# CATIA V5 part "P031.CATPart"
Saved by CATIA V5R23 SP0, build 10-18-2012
Part number: 05-LICP-T02-E-S05-P031
Definition: Rondelle ressort Ø 5.2
Description: Rondelle ressort Ø 5.2
Property "SUPPLIER": "NORELEM"
Property "REFERENCE": "NLM 07360-050"
Property "MATERIAL": "Acier à ressort"
Property "AUTHOR": "Trace Parts S.A."
Property "WEB": "www.traceparts.com"
Bounding box of the stored display mesh (mm): x -4.999 to 4.999, y -4.999 to 4.999, z 0 to 0.7
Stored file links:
  C:\wamp\www\COURS\CONCEPTION GMP1\TITRE 02-SEMESTRE 2\03-TP7-PRESSE MECANIQUE\eleve\P031.CATPart
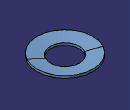
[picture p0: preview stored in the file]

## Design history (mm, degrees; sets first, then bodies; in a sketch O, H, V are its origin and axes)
Set1
  Plane1: type Offset, RefPlane xy-plane, Offset 0.7
Body1 (main body)
  Solid1: solid without history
